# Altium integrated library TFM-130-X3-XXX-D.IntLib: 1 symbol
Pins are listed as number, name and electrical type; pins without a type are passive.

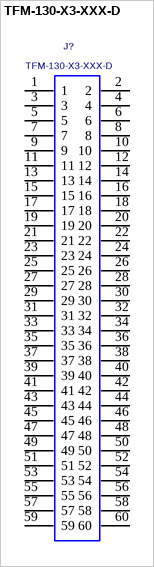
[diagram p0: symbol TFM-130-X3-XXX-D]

## TFM-130-X3-XXX-D
designator J?
0.050" TERMINAL STRIP, 30 PINS PER ROW.; MANUFACTURER: SAMTEC
footprint TFM-130-X3-XXX-D
pins: 1, 2, 3, 4, 5, 6, 7, 8, 9, 10, 11, 12, 13, 14, 15, 16, 17, 18, 19, 20, 21, 22, 23, 24, 25, 26, 27, 28, 29, 30, 31, 32, 33, 34, 35, 36, 37, 38, 39, 40, 41, 42, 43, 44, 45, 46, 47, 48, 49, 50, 51, 52, 53, 54, 55, 56, 57, 58, 59, 60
